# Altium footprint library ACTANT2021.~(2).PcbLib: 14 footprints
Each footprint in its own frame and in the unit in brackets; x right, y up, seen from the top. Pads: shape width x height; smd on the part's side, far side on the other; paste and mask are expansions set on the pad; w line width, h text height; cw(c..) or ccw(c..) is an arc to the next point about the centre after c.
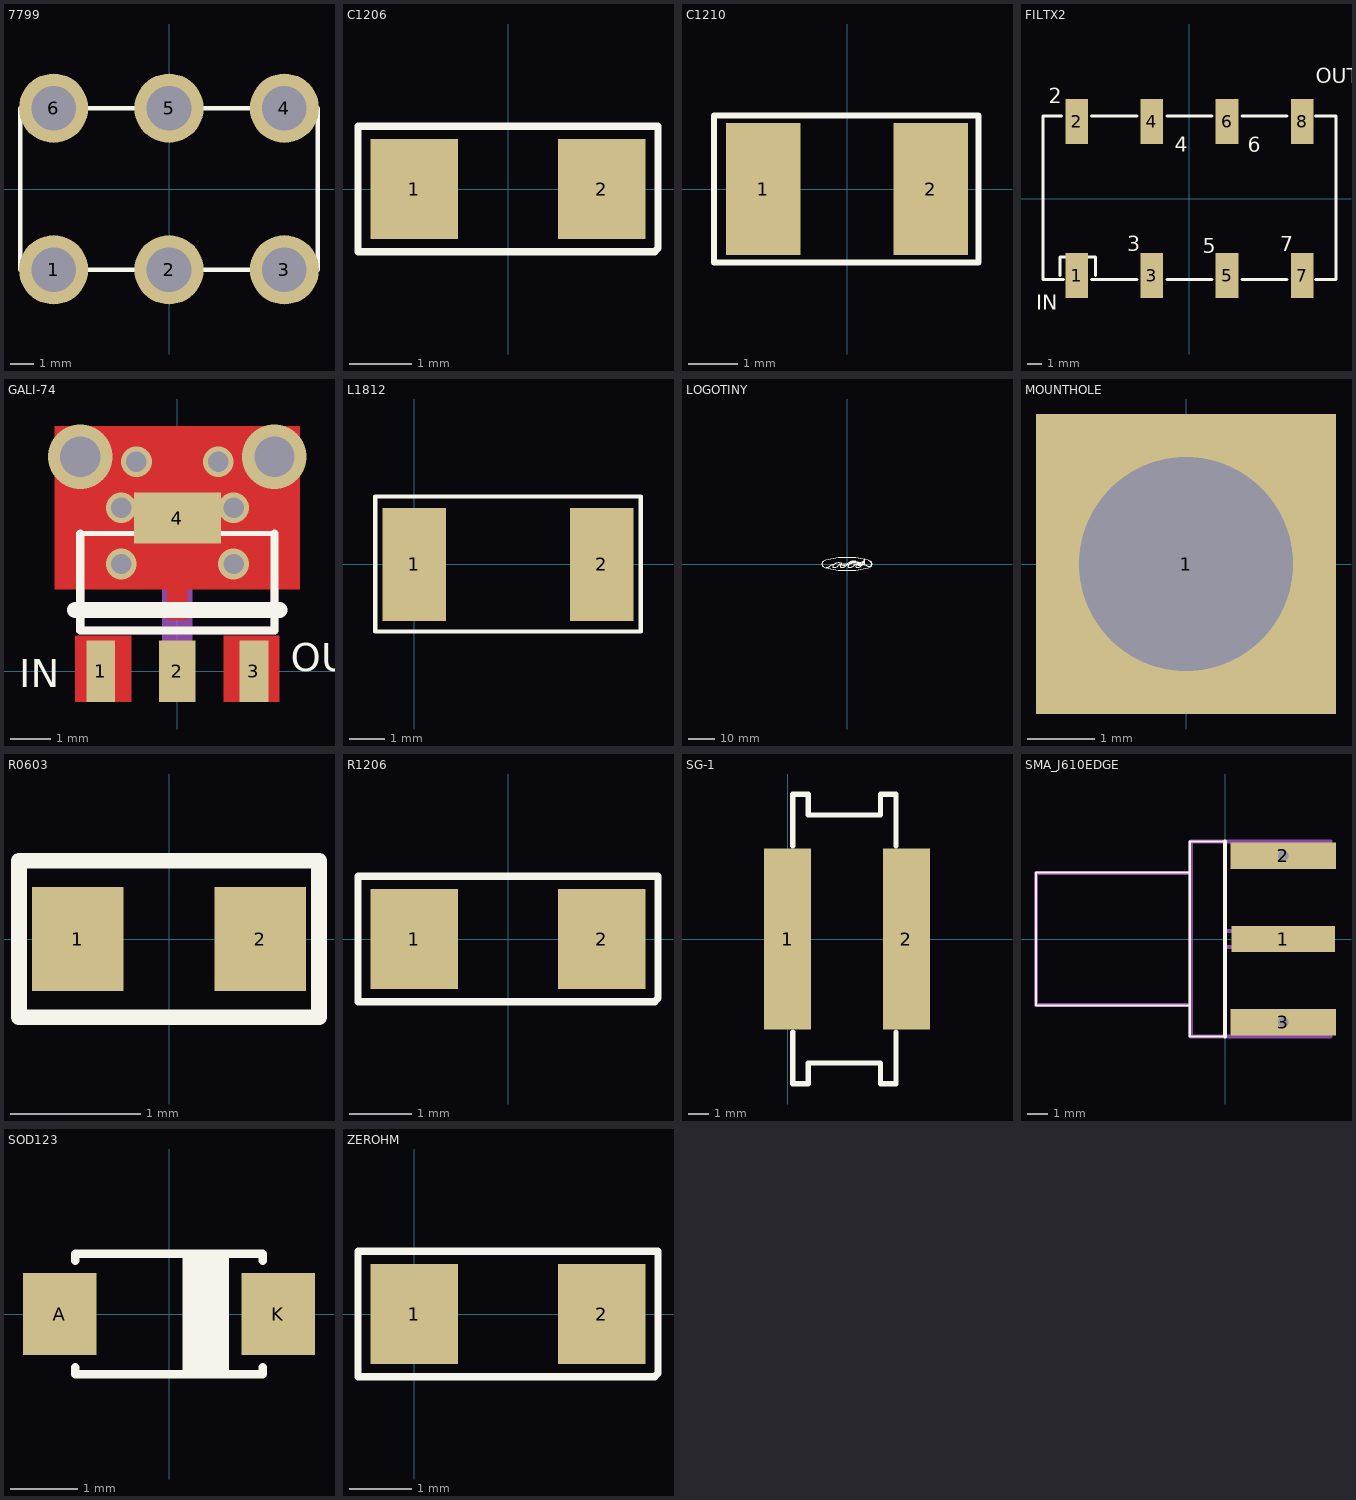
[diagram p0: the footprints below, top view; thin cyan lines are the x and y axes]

## 7799 [mm]
pads (6):
  round 3 hole 1.93 mask+0: 1(-5,-3.5) 2(0,-3.5) 3(5,-3.5) 4(5,3.5) 5(0,3.5) 6(-5,3.5)
Top Overlay:
  lines w0.2: -6.44,-3.5 6.44,-3.5 6.44,3.5 -6.44,3.5 -6.44,-3.5
3D body "keystone-PN7799.STEP": height 18.97, standoff -5.25, extent -6.428,-4.588 6.45,4.465

## C1206 [mm]
pads (2):
  rect 1.4x1.6 smd mask+0.05: 1(-1.5,0) 2(1.5,0)
Top Overlay:
  lines w0.12: -2.4,-1 -2.4,1 2.4,1 2.4,0.95 2.4,-0.95 2.35,-1 -2.4,-1
3D body "User Library-1206 SMD Resistor.step": height 1, standoff 0, extent -1.6,-0.8 1.6,0.8

## C1210 [mm]
pads (2):
  rect 1.524x2.7 smd: 1(-1.724,0) 2(1.705,0)
Top Overlay:
  lines w0.12: -2.725,-1.5 -2.725,1.5 2.675,1.5 2.675,-1.5 -2.725,-1.5
3D body "User Library-cap1210.STEP": height 0.95, standoff -0.01, extent -2.125,-1.351 2.075,1.349

## FILTX2 [mil]
pads (8):
  rect 60x120 smd: 1(-300,-205) 2(-300,205) 3(-100,-205) 4(-100,205) 5(100,-205) 6(100,205) 7(300,-205) 8(300,205)
Top Overlay:
  lines w8: -345,-205 -345,-155 -250,-155 -250,-205 ; -340,220 -390,220 -390,-215 -335,-215 ; -260,-215 -140,-215 ; -260,220 -140,220 ; -60,-215 60,-215 ; -60,220 60,220 ; 140,-215 260,-215 ; 140,220 260,220 ; 335,-215 390,-215 390,220 335,220
  text "2" at -374.67,254.34 h40
  text "4" at -39.72,125.19 h40
  text "6" at 155,123.99 h40
  text "3" at -165,-140 h40
  text "5" at 35,-145 h40
  text "7" at 241.54,-140.44 h40
  text "IN" at -408.31,-295.71 h40
  text "OUT" at 336.02,306.82 h40
Top Paste:
  rectangle: -327,148 -273,262
  rectangle: -127,148 -73,262
  rectangle: 73,148 127,262
  rectangle: 273,148 327,262
  rectangle: 73,-262 127,-148
  rectangle: 273,-262 327,-148
  rectangle: -127,-262 -73,-148
  rectangle: -327,-262 -273,-148

## GALI-74 [mil]
pads (4):
  rect 28x60 smd: 1(-75,0) 3(75,0)
  rect 36x60 smd: 2(0,0)
  rect 85x50 smd: 4(0,150)
via 55,160 diameter 30 hole 20
via -55,160 diameter 30 hole 20
via 55,105 diameter 30 hole 20
via -55,105 diameter 30 hole 20
via 40,205 diameter 30 hole 20
via -95,210 diameter 62.99 hole 39.37
via 95,210 diameter 62.99 hole 39.37
via -40,205 diameter 30 hole 20
Top Layer:
  region: 10,115 -10,115 -10,50 10,50
  region: -45,35 -100,35 -100,-30 -45,-30
  region: 100,35 45,35 45,-30 100,-30
  region: 120,240 -120,240 -120,80 120,80
Top Overlay:
  lines w5: -95,105 -95,135 -40,135 ; 40,135 95,135 95,105
  lines w8: -95,135 -95,40 95,40 95,135
  lines w16: -100,60 100,60
  text "OUT" at 111.07,0 h27.56
  text "IN" at -154.92,-15.55 h27.56
Top Paste:
  region: 16,28 -16,28 -16,-28 16,-28
  region: 40,195 -40,195 -40,120 40,120
Top Solder:
  region: 10,95 -10,95 -10,45 10,45
  region: 40,205 -40,205 -40,80 40,80
  region: 40,205 -40,205 -40,80 40,80
  region: -45,35 -100,35 -100,-30 -45,-30
  region: 100,35 45,35 45,-30 100,-30
  region: 10,175 -10,175 -10,15 10,15
  region: 40,205 -40,205 -40,80 40,80
Mechanical 3:
  lines w8: -35,140 -25,160 25,160 35,140 ; -95,40 95,40 95,135 -95,135 -95,40
  lines w30: 0,0 0,149
3D body "User Library-DF782.STEP": height 62.99, standoff 0, extent -90.55,-1.93 90.55,165

## L1812 [mm]
pads (2):
  rect 1.78x3.15 smd: 1(0,0) 2(5.23,0)
Top Overlay:
  lines w0.12: -1.091,-1.875 6.326,-1.875 6.326,1.9 -0.685,1.9 -1.091,1.9 -1.091,-1.875
3D body "User Library-Fuse 1812.STEP": height 1.03, standoff 0, extent 0.245,-1.737 4.98,1.743

## LOGOTINY [mm]
Top Overlay:
  lines w0.127: -7.721,-1.287 ccw(c-7.683,0.851) -6.145,-0.635 ; -6.137,-0.657 cw(c-5.22,-1.575) -4.884,-0.321 ; -4.99,-0.226 cw(c-3.124,-2.794) -2.039,0.188 ; -4.863,-1.287 ccw(c-4.826,0.851) -3.288,-0.635 ; -4.851,-1.295 cw(c-4.851,-0.813) -4.851,-0.33 ; -3.28,-0.657 cw(c-2.362,-1.575) -2.026,-0.321 ; -2.165,-0.252 ccw(c-1.079,2.73) 0.786,0.163 ; -2.051,0.193 ccw(c-0.965,3.175) 0.9,0.607 ; -2.007,-1.295 cw(c-2.007,-0.813) -2.007,-0.33 ; -1.993,-1.275 ccw(c-1.956,0.864) -0.417,-0.622 ; -0.422,-0.657 cw(c0.495,-1.575) 0.831,-0.321 ; 0.675,-0.29 cw(c2.54,-2.857) 3.625,0.125 ; 0.675,0.091 cw(c2.54,-2.476) 3.625,0.506 ; 0.675,0.472 cw(c2.54,-2.095) 3.625,0.887 ; 0.851,-1.295 cw(c0.851,-0.813) 0.851,-0.33 ; 0.852,-1.287 ccw(c0.889,0.851) 2.427,-0.635 ; 2.435,-0.657 cw(c3.353,-1.575) 3.689,-0.321 ; 3.614,-0.252 ccw(c4.699,2.73) 6.564,0.163 ; 3.614,0.129 ccw(c4.699,3.111) 6.564,0.544 ; 3.614,0.51 ccw(c4.699,3.492) 6.564,0.925 ; 3.614,0.891 ccw(c4.699,3.873) 6.564,1.306 ; 3.734,-1.295 cw(c3.734,-0.813) 3.734,-0.33 ; 3.747,-1.287 ccw(c3.785,0.851) 5.323,-0.635 ; 5.254,-0.657 cw(c6.172,-1.575) 6.172,-0.277 ; 6.159,-0.318 6.985,-0.318 ; 6.528,-0.318 6.528,1.956 ; 6.992,-0.325 ccw(c8.255,0.699) 8.993,-0.75 ; 8.302,1.16 cw(c7.925,0) 8.692,-0.947
  lines w0.203: -8.755,-1.04 cw(c-8.026,0) -8.755,1.04 ; -8.697,-1.082 ccw(c0,26.67) 8.697,-1.082 ; -8.697,1.082 cw(c0,-26.67) 8.697,1.082 ; 8.755,-1.04 ccw(c8.026,0) 8.755,1.04

## MOUNTHOLE [mm]
pads (1):
  rect 4.445x4.445 hole 3.175: 1(0,0)

## R0603 [mm]
pads (2):
  rect 0.7x0.8 smd mask+0.05: 1(-0.7,0) 2(0.7,0)
Top Overlay:
  lines w0.12: -1.15,-0.6 -1.15,-0.45 -1.15,0.6 1.15,0.6 1.15,-0.6 -1.15,-0.6
3D body "0603(1608M) Cap.step": height 0.79, standoff 0, extent -1,-0.394 1,0.394

## R1206 [mm]
pads (2):
  rect 1.4x1.6 smd mask+0.05: 1(-1.5,0) 2(1.5,0)
Top Overlay:
  lines w0.12: -2.4,-1 2.35,-1 2.4,-0.95 2.4,0.95 2.4,1 -2.4,1 -2.4,-1
3D body "User Library-1206 SMD Resistor.step": height 1, standoff 0, extent -1.6,-0.8 1.6,0.8

## SG-1 [mil]
pads (2):
  rect 90x350 smd: 1(0,0) 2(230,0)
Top Overlay:
  lines w10: 10,-180 10,-280 40,-280 40,-240 180,-240 180,-280 210,-280 210,-180 ; 10,180 10,280 40,280 40,240 180,240 180,280 210,280 210,180
Top Paste:
  region: 40,-170 40,170 -40,170 -40,-170
  region: 270,-170 270,170 190,170 190,-170
3D body "CG75MS.stp": height 250, standoff 0, extent -49.21,-183.07 277.56,183.08

## SMA_J610EDGE [mm]
pads (3):
  rect 5x1.27 smd: 1(2.8,0)
  rect 5.08x1.27 hole 0.5: 2(2.8,4) 3(2.8,-4)
Top Overlay:
  lines w0.1: -1.7,-3.2 -9.1,-3.2 -9.1,3.2 -1.7,3.2 ; 0,-4.699 -1.699,-4.699 -1.699,4.699 0,4.699
  lines w0.203: 0,-4.699 0,4.699
Mechanical 1:
  lines w0.203: -1.651,-3.175 -9.1,-3.175 -9.1,3.175 -1.651,3.175 ; 0,-0.381 4.699,-0.381 4.699,0.381 0,0.381 ; 5.08,-4.699 -1.651,-4.699 -1.651,4.699 5.08,4.699
3D body "732511150.stp": height 4.36, standoff -3.56, extent -9.144,-4.763 5.131,4.763

## SOD123 [mm]
pads (2):
  rect 1.1x1.22 smd: A(-1.635,0) K(1.635,0)
Top Overlay:
  rectangle: 0.2,-0.9 0.9,0.9
  lines w0.127: -1.4,-0.8 -1.4,-0.9 1.4,-0.9 1.4,-0.8 ; -1.4,0.8 -1.4,0.9 1.4,0.9 1.4,0.8
3D body "CircuitWorks-SOD123.STEP": height 1.27, standoff 0, extent -1.848,-0.805 1.852,0.795

## ZEROHM [mm]
pads (2):
  rect 1.4x1.6 smd mask+0.05: 1(0,0) 2(3,0)
Top Overlay:
  lines w0.12: -0.9,-1 3.85,-1 3.9,-0.95 3.9,0.95 3.9,1 -0.9,1 -0.9,-1
3D body "User Library-1206 SMD Resistor.step": height 1, standoff 0, extent -0.1,-0.8 3.1,0.8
